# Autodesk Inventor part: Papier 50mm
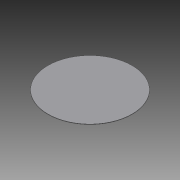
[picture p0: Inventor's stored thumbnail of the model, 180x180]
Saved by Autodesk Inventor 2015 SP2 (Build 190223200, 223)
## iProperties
Created: 2015-09
Part Number: Papier 50mm
Material: Allgemein
Document SubType Name: Modeling
Designer: ryll
Density: 1 g/cm^3
Appearance: Vorgabe
Mass: 1.35 g
Surface Area: 108.75 cm^2
Volume: 1.35 cm^3
Author: ryll
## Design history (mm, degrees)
sketch "Skizze1"
  geometry: L1 (0, 35)-(0, -35) reference; L2 (-35, 0)-(35, 0) reference; C1 r 25 at (0, 0)
  constraints: 2 midpoint, 1 centre point
  dimensions: "d4" = 50 diameter of C1
extrude "Extrusion1" new body sketch "Skizze1" distance "d2" = 0.25; taper "d3" = 0 deg
node "Volumenkörper1"
